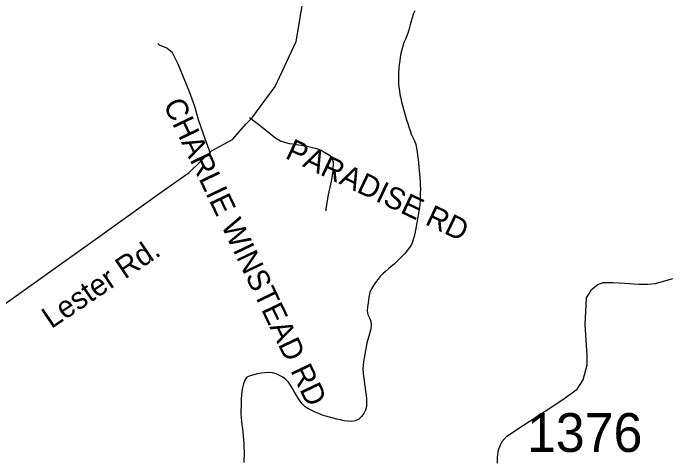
# Model space of a CAD drawing. Extents: x 1950930 to 2061844, y 904556 to 1017002.
# Drawn here: x 1993555 to 1996439, y 965716 to 967681 of the extents above; entities that cross this region are included whole.
import ezdxf

# ---------------------------------------------------------------- set-up
doc = ezdxf.new("R2010")
doc.units = 0
for name, color, linetype in [('Exist Hydrographic Creek Single Shore', 7, 'Continuous'), ('Exist Road Non-System Type 51', 7, 'Continuous'), ('Exist Road Non-System Type 51 Label', 7, 'Continuous'), ('Exist Road Secondary Type 51 Attributed', 7, 'Continuous'), ('Exist Road Secondary Type 51 Label', 7, 'Continuous'), ('Exist Road Secondary Type 51 Number Label', 7, 'Continuous')]:
    doc.layers.add(name, color=color, linetype=linetype)

msp = doc.modelspace()

# ---------------------------------------------------------------- linework, layer by layer
at = {"layer": 'Exist Hydrographic Creek Single Shore'}
for points in [[(1995314, 967691), (1995306.9, 967676.4), (1995301.5, 967660.9), (1995297.2, 967645.4), (1995293.5, 967629.1), (1995289.4, 967612.7), (1995284.7, 967597.2), (1995278.8, 967581.7), (1995272.2, 967566.3), (1995265.9, 967551.7), (1995260.5, 967536.2), (1995256.2, 967519.9), (1995252.9, 967504.3), (1995249.9, 967488)], [(1995249.9, 967488), (1995247.6, 967471.7), (1995245.4, 967455.3), (1995243.7, 967438.9), (1995242.5, 967422.5), (1995241.9, 967406.1), (1995241.9, 967389.7), (1995242.5, 967373.3), (1995243.9, 967356.9), (1995246, 967340.4), (1995248.6, 967324.7), (1995251.9, 967308.3)], [(1995251.9, 967308.3), (1995255.2, 967292.6), (1995259.1, 967276.1), (1995263.4, 967260.5), (1995267.9, 967244.8), (1995272.4, 967229.1), (1995277.3, 967213.5), (1995282.5, 967197.8), (1995287.6, 967182), (1995292.9, 967166.3), (1995297.8, 967150.6), (1995304.4, 967135.7), (1995311.8, 967120.8), (1995317.5, 967105.9), (1995320.6, 967089.4), (1995323.5, 967073.8), (1995325.7, 967057.3), (1995327.8, 967040.8), (1995329.6, 967024.4), (1995331.3, 967008), (1995332.9, 966991.5), (1995334.1, 966975.9), (1995335.4, 966959.5), (1995336.6, 966943), (1995337.4, 966926.6), (1995338, 966910.2), (1995337.6, 966893.8), (1995337.4, 966877.4), (1995336.6, 966861.1), (1995335.4, 966844.6), (1995333.9, 966828.3), (1995331.5, 966811.9), (1995328.8, 966795.6), (1995325.7, 966779.2), (1995322.9, 966762.9), (1995320, 966746.4), (1995316.9, 966730.1), (1995313.2, 966714.6), (1995309.3, 966698.3), (1995304.6, 966682.8), (1995299.3, 966668.1), (1995290.9, 966653.6), (1995280.6, 966640.6), (1995269.3, 966628.5), (1995258.3, 966616.4), (1995246.6, 966604.4), (1995234.9, 966593.2), (1995222.8, 966582), (1995210.7, 966570.7), (1995198.6, 966560.3), (1995185.5, 966549.9), (1995173, 966539.4), (1995161.9, 966527.3), (1995151.8, 966514.4), (1995142, 966501.6), (1995132.2, 966487.9), (1995123.3, 966474), (1995117, 966459.4), (1995113.5, 966443.1), (1995111.2, 966426.7), (1995109.4, 966410.4), (1995106.9, 966394.1), (1995105.5, 966377.6), (1995107.4, 966361.2), (1995114.7, 966346.3), (1995120.9, 966331.3), (1995122.1, 966314.9), (1995120.7, 966298.5), (1995117, 966282.2), (1995112.3, 966266.7), (1995107.4, 966251.2), (1995103.7, 966234.8), (1995100.4, 966219.4), (1995097.9, 966203.1), (1995094.8, 966186.7), (1995091.6, 966170.4), (1995088.9, 966153.9), (1995087.1, 966137.5), (1995086.6, 966121.2), (1995087.7, 966105.6), (1995089.1, 966089.2), (1995091.2, 966072.6), (1995093.6, 966056.2), (1995095.9, 966039.7), (1995098.1, 966023.3), (1995100.2, 966006.9), (1995101.6, 965990.4), (1995102.2, 965974), (1995101.8, 965958.4), (1995097.5, 965942.1), (1995089.9, 965926.6), (1995079.9, 965913.7), (1995067.8, 965902.6), (1995052.2, 965894.7), (1995036.2, 965892.5), (1995020.2, 965893.6), (1995004.4, 965895.6), (1994988, 965899.3), (1994971.8, 965902.9), (1994955.4, 965907.3)], [(1994955.4, 965907.3), (1994939.4, 965911.8), (1994923.6, 965915.3), (1994908, 965920.6), (1994892.7, 965926.6), (1994877.7, 965933.5), (1994862.7, 965940.4), (1994848.2, 965948.1), (1994834.2, 965956.6), (1994822.5, 965968.3), (1994812.3, 965980.8), (1994802.9, 965994.9), (1994794, 966008.3), (1994786, 966023.2), (1994778, 966037.3), (1994769.6, 966051.4), (1994760.2, 966064.8), (1994748.5, 966075.7), (1994735.2, 966085.8), (1994721.2, 966094.3), (1994705.9, 966100.4), (1994689.9, 966105.7), (1994673.9, 966106.8), (1994657.5, 966105.5), (1994641.3, 966103.3), (1994624.9, 966100.4), (1994608.7, 966096.6), (1994592.3, 966092.8), (1994577.5, 966085.8), (1994568.9, 966072.9), (1994563.4, 966056.5), (1994558.8, 966040.2), (1994556, 966023.8), (1994554.3, 966007.5), (1994553.5, 965991.1), (1994553.1, 965974.7), (1994552.7, 965958.3), (1994552.5, 965941.9), (1994552.5, 965925.5), (1994553.1, 965909), (1994554.5, 965893.4), (1994556.4, 965877), (1994558.4, 965860.5), (1994560.5, 965844.1), (1994562.3, 965827.6), (1994563.6, 965811.2), (1994564.8, 965794.8), (1994565.6, 965779.2), (1994566.4, 965762.7), (1994566.6, 965746.3), (1994565.2, 965729.1), (1994564.4, 965712.8)]]:
    msp.add_lwpolyline(points, dxfattribs=at)
at = {"layer": 'Exist Road Non-System Type 51'}
for points in [[(1994418.5, 967066.6), (1994395.9, 967130.1), (1994366.4, 967212.9), (1994350.9, 967271.4), (1994327.5, 967336.4), (1994277.6, 967457.5), (1994252.6, 967507), (1994228.4, 967527.9), (1994196.1, 967541.2), (1994188.9, 967547.2)], [(1994589.6, 967224.4), (1994625.1, 967196.9), (1994703.8, 967134.4), (1994725.8, 967121.6), (1994747.5, 967114.4), (1994763.6, 967110.3), (1994777.4, 967108.7), (1994804.4, 967104.7), (1994834.6, 967100.2), (1994853.2, 967095.8), (1994883, 967088.1), (1994903.2, 967080.5), (1994940, 967058.5), (1994951.9, 967041.8), (1994955.8, 967028.9), (1994955.8, 967017.1), (1994954.8, 967003.4), (1994954.8, 966986.6), (1994946.9, 966945.2), (1994938, 966905.9), (1994932.1, 966877.3), (1994924.2, 966823.1), (1994923.5, 966815.1)], [(1995675.5, 965710.4), (1995676.2, 965735.7), (1995680.4, 965768.8), (1995694.1, 965803.6), (1995716, 965827.5), (1995789.8, 965876.7), (1995884.8, 965937.9), (1995962.1, 965988.6), (1996023.8, 966033.2), (1996051.1, 966075.4), (1996068, 966140.1), (1996068, 966182.4), (1996059.9, 966314.9), (1996065.2, 966433.4), (1996075, 966449.6), (1996087.8, 966470.1), (1996115.1, 966492.6), (1996138.4, 966501), (1996182.6, 966501.7), (1996233.4, 966497.5), (1996293.8, 966493.2), (1996333.9, 966493.2), (1996367, 966496.1), (1996443.2, 966518.9)]]:
    msp.add_lwpolyline(points, dxfattribs=at)
at = {"layer": 'Exist Road Secondary Type 51 Attributed'}
msp.add_lwpolyline([(1993108.8, 966020.9), (1993177.1, 966103.9), (1993238.8, 966184.2), (1993448.3, 966356.8), (1993507.5, 966398.9), (1993695.7, 966532.6), (1993924.2, 966696.2), (1994192.7, 966889.7), (1994324.9, 966983.4), (1994423.1, 967077.2), (1994515.1, 967127.1), (1994573.4, 967194.5), (1994600.4, 967220.7), (1994702.7, 967360.1), (1994793.7, 967556.3), (1994838.5, 967818.2)], dxfattribs=at)

# ---------------------------------------------------------------- texts
at = {"layer": 'Exist Road Non-System Type 51 Label'}
for s, rotation, p in [('  CHARLIE WINSTEAD RD', 295.5512, (1994180.1, 967345)), ('  PARADISE RD', 334.6803, (1994677.7, 967077.6))]:
    msp.add_text(s, height=95, rotation=rotation, dxfattribs=at).set_placement(p)
at = {"layer": 'Exist Road Secondary Type 51 Label'}
msp.add_text('Lester Rd.', height=95, rotation=33.9634, dxfattribs=at).set_placement((1993721.9, 966296.3))
at = {"layer": 'Exist Road Secondary Type 51 Number Label'}
msp.add_text('1376', height=170, dxfattribs=at).set_placement((1995804.3, 965758.9))

doc.saveas('drawing.dxf')
